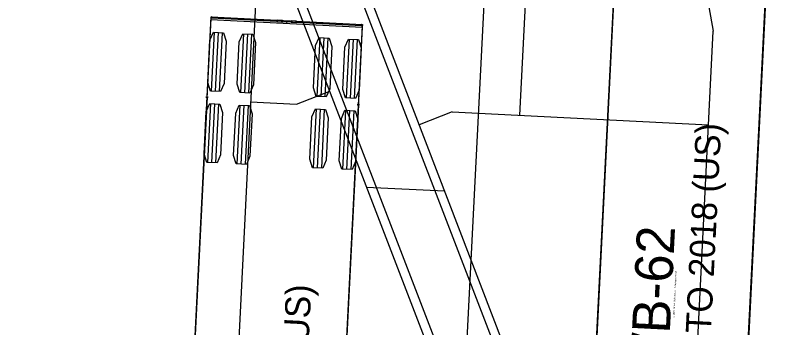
# Model space of a CAD drawing. Extents: x 260275 to 261282, y 610916 to 614143.
# Drawn here: x 261019.98 to 261062.63, y 612093.2 to 612110.71 of the extents above; entities that cross this region are included whole.
import ezdxf

# ---------------------------------------------------------------- set-up
doc = ezdxf.new("R2010")
doc.units = 0
for name, color, linetype in [('DR_P_Ditch', 7, 'Continuous'), ('GE_X_Alignment', 7, 'Continuous'), ('PV_P_Curb', 7, 'Continuous'), ('PV_P_EOP', 7, 'Continuous'), ('PV_P_Joint', 7, 'Continuous'), ('TopoDOT_Transients', 7, 'Continuous'), ('UT_X_Water_Cells', 7, 'Continuous')]:
    doc.layers.add(name, color=color, linetype=linetype)

msp = doc.modelspace()

# ---------------------------------------------------------------- linework, layer by layer
at = {"layer": 'DR_P_Ditch'}
msp.add_line((261039.686, 612101.085), (261044.056, 612100.865), dxfattribs=at)
at = {"layer": 'GE_X_Alignment'}
msp.add_line((260986.249, 610915.954), (261148.276, 614142.838), dxfattribs=at)
at = {"layer": 'PV_P_Curb'}
for p, q in [((261034.244, 612116.627), (261053.627, 612066.228)), ((261037.345, 612116.921), (261056.48, 612067.167)), ((261034.545, 612115.844), (261053.68, 612066.09))]:
    msp.add_line(p, q, dxfattribs=at)
at = {"layer": 'PV_P_EOP'}
for p, q in [((261045.432, 612188.236), (261059.122, 612109.815)), ((261037.86, 612116.976), (261056.985, 612067.248)), ((261031.212, 612066.209), (261033.739, 612116.547)), ((261033.739, 612116.547), (261053.122, 612066.147)), ((261056.985, 612067.248), (261059.122, 612109.815))]:
    msp.add_line(p, q, dxfattribs=at)
at = {"layer": 'PV_P_Joint'}
for p, q in [((261050.523, 612150.048), (261048.266, 612105.105)), ((261035.755, 612105.733), (261037.622, 612106.451)), ((261033.181, 612105.862), (261035.755, 612105.733)), ((261044.495, 612105.294), (261042.629, 612104.576)), ((261044.495, 612105.294), (261058.869, 612104.572))]:
    msp.add_line(p, q, dxfattribs=at)
at = {"layer": 'TopoDOT_Transients'}
for points in [[(261051.548, 612071.863), (261074.206, 612523.277)], [(261082.631, 612521.243), (261060.03, 612071.291), (261051.541, 612071.717), (261051.548, 612071.863), (261051.548, 612071.863)], [(261060.011, 612071.363), (261060.033, 612071.362), (261062.437, 612119.231), (261058.192, 612119.444), (261053.948, 612119.657), (261051.544, 612071.788), (261051.567, 612071.787)], [(261051.766, 612076.212), (261051.933, 612079.541), (261052.101, 612082.871), (261052.268, 612086.2), (261052.435, 612089.53), (261052.602, 612092.859), (261052.769, 612096.189), (261052.937, 612099.519), (261053.104, 612102.848), (261053.271, 612106.178), (261053.438, 612109.507), (261053.605, 612112.837)], [(261060.256, 612075.785), (261060.423, 612079.115), (261060.59, 612082.445), (261060.757, 612085.774), (261060.924, 612089.104), (261061.091, 612092.433), (261061.259, 612095.763), (261061.426, 612099.092), (261061.593, 612102.422), (261061.76, 612105.751), (261061.927, 612109.081), (261062.095, 612112.41)]]:
    msp.add_lwpolyline(points, dxfattribs=at)
at = {"layer": 'UT_X_Water_Cells'}
for p, q in [((261030.958, 612110.476), (261039.448, 612110.05)), ((261034.676, 612110.36), (261034.941, 612110.347)), ((261035.466, 612110.321), (261034.943, 612110.347)), ((261035.207, 612110.334), (261035.203, 612110.263)), ((261035.472, 612110.32), (261035.737, 612110.307)), ((261030.986, 612106.461), (261031.152, 612109.757)), ((261031.215, 612106.449), (261031.381, 612109.745)), ((261031.444, 612106.438), (261031.609, 612109.734)), ((261032.634, 612106.378), (261032.8, 612109.674)), ((261032.863, 612106.367), (261033.029, 612109.662)), ((261033.092, 612106.355), (261033.257, 612109.651)), ((261036.912, 612106.163), (261037.078, 612109.459)), ((261037.141, 612106.152), (261037.306, 612109.448)), ((261037.37, 612106.14), (261037.535, 612109.436)), ((261038.56, 612106.081), (261038.726, 612109.376)), ((261038.789, 612106.069), (261038.954, 612109.365)), ((261039.018, 612106.058), (261039.183, 612109.353)), ((261030.786, 612102.466), (261030.951, 612105.762)), ((261031.015, 612102.454), (261031.18, 612105.75)), ((261031.243, 612102.443), (261031.409, 612105.739)), ((261032.434, 612102.383), (261032.599, 612105.679)), ((261032.662, 612102.372), (261032.828, 612105.668)), ((261032.891, 612102.36), (261033.057, 612105.656)), ((261036.712, 612102.168), (261036.877, 612105.464)), ((261036.94, 612102.157), (261037.106, 612105.453)), ((261037.169, 612102.145), (261037.335, 612105.441)), ((261038.359, 612102.086), (261038.525, 612105.381)), ((261038.588, 612102.074), (261038.754, 612105.37)), ((261038.817, 612102.063), (261038.983, 612105.358))]:
    msp.add_line(p, q, dxfattribs=at)
for points in [[(261009.34, 611680.102), (261030.965, 612110.617), (261039.455, 612110.191), (261039.447, 612110.045), (261039.447, 612110.045)], [(261030.984, 612110.546), (261030.962, 612110.547), (261028.558, 612062.678), (261032.803, 612062.464), (261037.048, 612062.251), (261039.451, 612110.12), (261039.429, 612110.122)], [(261034.947, 612110.417), (261034.681, 612110.431), (261034.68, 612110.43), (261034.676, 612110.36), (261034.64, 612110.362), (261031.009, 612110.544), (261031.008, 612110.544)], [(261039.405, 612110.123), (261039.404, 612110.123), (261035.773, 612110.305), (261035.737, 612110.307), (261035.741, 612110.377), (261035.739, 612110.377), (261035.473, 612110.391)], [(261039.447, 612110.045), (261018.12, 611685.301)], [(261030.74, 612106.123), (261030.573, 612102.794), (261030.406, 612099.466), (261030.238, 612096.137), (261030.071, 612092.808), (261029.904, 612089.48), (261029.737, 612086.151), (261029.57, 612082.822), (261029.403, 612079.494), (261029.236, 612076.165), (261029.068, 612072.836), (261028.901, 612069.508), (261028.734, 612066.179), (261028.567, 612062.85), (261028.4, 612059.522), (261028.233, 612056.193)], [(261039.229, 612105.697), (261039.062, 612102.368), (261038.895, 612099.039), (261038.728, 612095.711), (261038.561, 612092.382), (261038.393, 612089.053), (261038.226, 612085.725), (261038.059, 612082.396), (261037.892, 612079.067), (261037.725, 612075.739), (261037.558, 612072.41), (261037.391, 612069.081), (261037.223, 612065.753), (261037.056, 612062.424), (261036.889, 612059.095)]]:
    msp.add_lwpolyline(points, dxfattribs=at)
for points in [[(261031.501, 612106.435), (261030.929, 612106.464), (261030.781, 612106.934), (261030.9, 612109.307), (261031.095, 612109.76), (261031.666, 612109.731), (261031.815, 612109.261), (261031.696, 612106.888)], [(261033.149, 612106.352), (261032.577, 612106.381), (261032.428, 612106.851), (261032.548, 612109.224), (261032.743, 612109.677), (261033.314, 612109.648), (261033.463, 612109.178), (261033.344, 612106.805)], [(261037.427, 612106.138), (261036.855, 612106.166), (261036.706, 612106.636), (261036.826, 612109.009), (261037.021, 612109.462), (261037.592, 612109.433), (261037.741, 612108.963), (261037.622, 612106.59)], [(261039.075, 612106.055), (261038.503, 612106.083), (261038.354, 612106.554), (261038.473, 612108.927), (261038.669, 612109.379), (261039.24, 612109.351), (261039.389, 612108.881), (261039.27, 612106.508)], [(261031.3, 612102.44), (261030.729, 612102.469), (261030.58, 612102.939), (261030.699, 612105.312), (261030.894, 612105.765), (261031.466, 612105.736), (261031.615, 612105.266), (261031.495, 612102.893)], [(261032.948, 612102.357), (261032.377, 612102.386), (261032.228, 612102.856), (261032.347, 612105.229), (261032.542, 612105.682), (261033.114, 612105.653), (261033.263, 612105.183), (261033.143, 612102.81)], [(261037.226, 612102.143), (261036.655, 612102.171), (261036.506, 612102.641), (261036.625, 612105.014), (261036.82, 612105.467), (261037.392, 612105.438), (261037.54, 612104.968), (261037.421, 612102.595)], [(261038.874, 612102.06), (261038.303, 612102.088), (261038.154, 612102.559), (261038.273, 612104.932), (261038.468, 612105.384), (261039.039, 612105.356), (261039.188, 612104.886), (261039.069, 612102.513)]]:
    msp.add_lwpolyline(points, close=True, dxfattribs=at)
for centre, radius in [((261030.998, 612110.579), 0.0266), ((261039.419, 612110.156), 0.0266), ((261030.74, 612106.123), 0.0417), ((261039.229, 612105.697), 0.0417)]:
    msp.add_circle(centre, radius, dxfattribs=at)
for centre, radius, start, end in [((261030.998, 612110.579), 0.0363, 286.8861, 248.0487), ((261034.945, 612110.382), 0.0354, 91.417, 263.6025), ((261034.945, 612110.382), 0.0352, 266.5234, 87.1099), ((261035.472, 612110.356), 0.0352, 87.1411, 267.7276), ((261035.472, 612110.355), 0.0352, 266.913, 89.5524), ((261039.419, 612110.156), 0.0363, 286.2023, 247.3649)]:
    msp.add_arc(centre, radius, start, end, dxfattribs=at)

# ---------------------------------------------------------------- texts
at = {"layer": 'TopoDOT_Transients'}
for s, height, p in [('AASHTO 2018 (US)', 1.41667, (261058.734, 612087.712)), ('WB-62', 2.125, (261056.553, 612090.177)), ('(c) 2023 Transoft Solutions, Inc. All rights reserved.', 0.085, (261056.944, 612093.734))]:
    msp.add_text(s, height=height, rotation=87.1255, dxfattribs=at).set_placement(p)
at = {"layer": 'UT_X_Water_Cells'}
msp.add_text('AASHTO 2018 (US)', height=1.41667, rotation=87.1255, dxfattribs=at).set_placement((261035.752, 612078.672))

doc.saveas('drawing.dxf')
